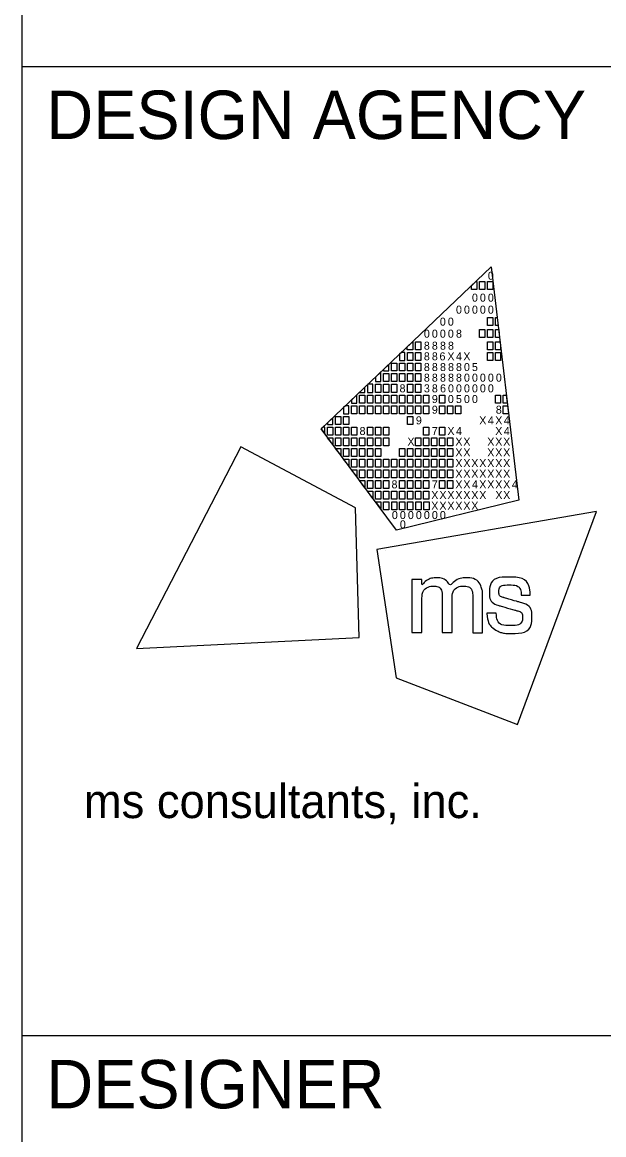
# Model space of a CAD drawing. Extents: x -3.6 to 34, y 0 to 22.
# Drawn here: x 32 to 33.201, y 2.295 to 4.591 of the extents above; entities that cross this region are included whole.
import ezdxf

# ---------------------------------------------------------------- set-up
doc = ezdxf.new("R2010")
doc.units = 0
for name, color, linetype in [('Default', 7, 'Continuous'), ('SH_Border', 7, 'Continuous'), ('SH_Data', 7, 'Continuous')]:
    doc.layers.add(name, color=color, linetype=linetype)

msp = doc.modelspace()

# ---------------------------------------------------------------- linework, layer by layer
at = {"layer": 'Default'}
for p, q in [((32.6175, 3.7519), (32.9688, 4.0861)), ((32.9688, 4.0861), (32.9688, 4.0861)), ((32.9688, 4.0861), (33.0253, 3.6052)), ((32.773, 3.543), (32.6175, 3.7519)), ((33.0253, 3.6052), (32.773, 3.543))]:
    msp.add_line(p, q, dxfattribs=at)
for points in [[(32.9279, 4.0472), (32.9369, 4.0558), (32.9389, 4.0558), (32.9389, 4.0393), (32.9279, 4.0393)], [(32.9444, 4.0558), (32.9554, 4.0558), (32.9554, 4.0393), (32.9444, 4.0393)], [(32.9609, 4.0558), (32.9719, 4.0558), (32.9719, 4.0393), (32.9609, 4.0393)], [(32.9606, 3.9815), (32.9716, 3.9815), (32.9716, 3.965), (32.9606, 3.965)], [(32.9771, 3.9815), (32.9811, 3.9815), (32.983, 3.965), (32.9771, 3.965)], [(32.9441, 3.9567), (32.9551, 3.9567), (32.9551, 3.9402), (32.9441, 3.9402)], [(32.9606, 3.9567), (32.9716, 3.9567), (32.9716, 3.9402), (32.9606, 3.9402)], [(32.9771, 3.9567), (32.984, 3.9567), (32.9859, 3.9402), (32.9771, 3.9402)], [(32.7953, 3.9211), (32.8064, 3.9316), (32.8064, 3.9154), (32.7953, 3.9154)], [(32.8123, 3.9319), (32.8233, 3.9319), (32.8233, 3.9154), (32.8123, 3.9154)], [(32.9606, 3.9319), (32.9716, 3.9319), (32.9716, 3.9154), (32.9606, 3.9154)], [(32.9771, 3.9319), (32.9869, 3.9319), (32.9881, 3.9218), (32.9881, 3.9154), (32.9771, 3.9154)], [(32.7958, 3.9099), (32.8068, 3.9099), (32.8068, 3.8934), (32.7958, 3.8934)], [(32.8123, 3.9099), (32.8233, 3.9099), (32.8233, 3.8934), (32.8123, 3.8934)], [(32.9606, 3.9099), (32.9716, 3.9099), (32.9716, 3.8934), (32.9606, 3.8934)], [(32.9771, 3.9099), (32.9881, 3.9099), (32.9881, 3.8934), (32.9771, 3.8934)], [(32.7627, 3.8879), (32.7737, 3.8879), (32.7737, 3.8714), (32.7627, 3.8714)], [(32.7793, 3.8879), (32.7903, 3.8879), (32.7903, 3.8714), (32.7793, 3.8714)], [(32.7958, 3.8879), (32.8068, 3.8879), (32.8068, 3.8714), (32.7958, 3.8714)], [(32.8123, 3.8879), (32.8233, 3.8879), (32.8233, 3.8714), (32.8123, 3.8714)], [(32.7462, 3.8659), (32.7572, 3.8659), (32.7572, 3.8494), (32.7462, 3.8494)], [(32.7627, 3.8659), (32.7737, 3.8659), (32.7737, 3.8494), (32.7627, 3.8494)], [(32.7793, 3.8659), (32.7903, 3.8659), (32.7903, 3.8494), (32.7793, 3.8494)], [(32.7958, 3.8659), (32.8068, 3.8659), (32.8068, 3.8494), (32.7958, 3.8494)], [(32.8123, 3.8659), (32.8233, 3.8659), (32.8233, 3.8494), (32.8123, 3.8494)], [(32.7297, 3.8439), (32.7407, 3.8439), (32.7407, 3.8273), (32.7297, 3.8273)], [(32.7462, 3.8439), (32.7572, 3.8439), (32.7572, 3.8273), (32.7462, 3.8273)], [(32.7627, 3.8439), (32.7737, 3.8439), (32.7737, 3.8273), (32.7627, 3.8273)], [(32.7958, 3.8439), (32.8068, 3.8439), (32.8068, 3.8273), (32.7958, 3.8273)], [(32.8123, 3.8439), (32.8233, 3.8439), (32.8233, 3.8273), (32.8123, 3.8273)], [(32.6967, 3.8218), (32.7077, 3.8218), (32.7077, 3.8053), (32.6967, 3.8053)], [(32.7132, 3.8218), (32.7242, 3.8218), (32.7242, 3.8053), (32.7132, 3.8053)], [(32.7297, 3.8218), (32.7407, 3.8218), (32.7407, 3.8053), (32.7297, 3.8053)], [(32.7462, 3.8218), (32.7572, 3.8218), (32.7572, 3.8053), (32.7462, 3.8053)], [(32.7627, 3.8218), (32.7737, 3.8218), (32.7737, 3.8053), (32.7627, 3.8053)], [(32.7793, 3.8218), (32.7903, 3.8218), (32.7903, 3.8053), (32.7793, 3.8053)], [(32.7958, 3.8218), (32.8068, 3.8218), (32.8068, 3.8053), (32.7958, 3.8053)], [(32.8123, 3.8218), (32.8233, 3.8218), (32.8233, 3.8053), (32.8123, 3.8053)], [(32.8288, 3.8218), (32.8398, 3.8218), (32.8398, 3.8053), (32.8288, 3.8053)], [(32.8618, 3.8218), (32.8728, 3.8218), (32.8728, 3.8053), (32.8618, 3.8053)], [(32.9771, 3.8218), (32.9881, 3.8218), (32.9881, 3.8053), (32.9771, 3.8053)], [(32.9935, 3.8218), (32.9998, 3.8218), (33.0018, 3.8053), (32.9935, 3.8053)], [(32.6802, 3.7998), (32.6912, 3.7998), (32.6912, 3.7833), (32.6802, 3.7833)], [(32.6967, 3.7998), (32.7077, 3.7998), (32.7077, 3.7833), (32.6967, 3.7833)], [(32.7132, 3.7998), (32.7242, 3.7998), (32.7242, 3.7833), (32.7132, 3.7833)], [(32.7297, 3.7998), (32.7407, 3.7998), (32.7407, 3.7833), (32.7297, 3.7833)], [(32.7462, 3.7998), (32.7572, 3.7998), (32.7572, 3.7833), (32.7462, 3.7833)], [(32.7627, 3.7998), (32.7737, 3.7998), (32.7737, 3.7833), (32.7627, 3.7833)], [(32.7793, 3.7998), (32.7903, 3.7998), (32.7903, 3.7833), (32.7793, 3.7833)], [(32.7958, 3.7998), (32.8068, 3.7998), (32.8068, 3.7833), (32.7958, 3.7833)], [(32.8123, 3.7998), (32.8233, 3.7998), (32.8233, 3.7833), (32.8123, 3.7833)], [(32.8288, 3.7998), (32.8398, 3.7998), (32.8398, 3.7833), (32.8288, 3.7833)], [(32.8618, 3.7998), (32.8728, 3.7998), (32.8728, 3.7833), (32.8618, 3.7833)], [(32.8783, 3.7998), (32.8893, 3.7998), (32.8893, 3.7833), (32.8783, 3.7833)], [(32.8947, 3.7998), (32.9057, 3.7998), (32.9057, 3.7833), (32.8947, 3.7833)], [(32.9935, 3.7998), (33.0024, 3.7998), (33.0044, 3.7833), (32.9935, 3.7833)], [(32.6471, 3.7778), (32.6581, 3.7778), (32.6581, 3.7613), (32.6471, 3.7613)], [(32.6637, 3.7778), (32.6747, 3.7778), (32.6747, 3.7613), (32.6637, 3.7613)], [(32.7958, 3.7778), (32.8068, 3.7778), (32.8068, 3.7613), (32.7958, 3.7613)], [(32.6306, 3.7558), (32.6416, 3.7558), (32.6416, 3.7393), (32.6306, 3.7393)], [(32.6471, 3.7558), (32.6581, 3.7558), (32.6581, 3.7393), (32.6471, 3.7393)], [(32.6637, 3.7558), (32.6747, 3.7558), (32.6747, 3.7393), (32.6637, 3.7393)], [(32.6802, 3.7558), (32.6912, 3.7558), (32.6912, 3.7393), (32.6802, 3.7393)], [(32.7132, 3.7558), (32.7242, 3.7558), (32.7242, 3.7393), (32.7132, 3.7393)], [(32.7297, 3.7558), (32.7407, 3.7558), (32.7407, 3.7393), (32.7297, 3.7393)], [(32.7462, 3.7558), (32.7572, 3.7558), (32.7572, 3.7393), (32.7462, 3.7393)], [(32.8288, 3.7558), (32.8398, 3.7558), (32.8398, 3.7393), (32.8288, 3.7393)], [(32.8618, 3.7558), (32.8728, 3.7558), (32.8728, 3.7393), (32.8618, 3.7393)], [(32.6306, 3.7338), (32.6416, 3.7338), (32.6416, 3.72)], [(32.6471, 3.7338), (32.6581, 3.7338), (32.6581, 3.7173), (32.6471, 3.7173)], [(32.6637, 3.7338), (32.6747, 3.7338), (32.6747, 3.7173), (32.6637, 3.7173)], [(32.6802, 3.7338), (32.6912, 3.7338), (32.6912, 3.7173), (32.6802, 3.7173)], [(32.6967, 3.7338), (32.7077, 3.7338), (32.7077, 3.7173), (32.6967, 3.7173)], [(32.7132, 3.7338), (32.7242, 3.7338), (32.7242, 3.7173), (32.7132, 3.7173)], [(32.7297, 3.7338), (32.7407, 3.7338), (32.7407, 3.7173), (32.7297, 3.7173)], [(32.7462, 3.7338), (32.7572, 3.7338), (32.7572, 3.7173), (32.7462, 3.7173)], [(32.8123, 3.7338), (32.8233, 3.7338), (32.8233, 3.7173), (32.8123, 3.7173)], [(32.8288, 3.7338), (32.8398, 3.7338), (32.8398, 3.7173), (32.8288, 3.7173)], [(32.8453, 3.7338), (32.8563, 3.7338), (32.8563, 3.7173), (32.8453, 3.7173)], [(32.8618, 3.7338), (32.8728, 3.7338), (32.8728, 3.7173), (32.8618, 3.7173)], [(32.8783, 3.7338), (32.8893, 3.7338), (32.8893, 3.7173), (32.8783, 3.7173)], [(32.6471, 3.7117), (32.6581, 3.7117), (32.6581, 3.698)], [(32.6637, 3.7117), (32.6747, 3.7117), (32.6747, 3.6952), (32.6637, 3.6952)], [(32.6802, 3.7117), (32.6912, 3.7117), (32.6912, 3.6952), (32.6802, 3.6952)], [(32.6967, 3.7117), (32.7077, 3.7117), (32.7077, 3.6952), (32.6967, 3.6952)], [(32.7132, 3.7117), (32.7242, 3.7117), (32.7242, 3.6952), (32.7132, 3.6952)], [(32.7297, 3.7117), (32.7407, 3.7117), (32.7407, 3.6952), (32.7297, 3.6952)], [(32.7793, 3.7117), (32.7903, 3.7117), (32.7903, 3.6952), (32.7793, 3.6952)], [(32.7958, 3.7117), (32.8068, 3.7117), (32.8068, 3.6952), (32.7958, 3.6952)], [(32.8123, 3.7117), (32.8233, 3.7117), (32.8233, 3.6952), (32.8123, 3.6952)], [(32.8288, 3.7117), (32.8398, 3.7117), (32.8398, 3.6952), (32.8288, 3.6952)], [(32.8453, 3.7117), (32.8563, 3.7117), (32.8563, 3.6952), (32.8453, 3.6952)], [(32.8618, 3.7117), (32.8728, 3.7117), (32.8728, 3.6952), (32.8618, 3.6952)], [(32.8783, 3.7117), (32.8893, 3.7117), (32.8893, 3.6952), (32.8783, 3.6952)], [(32.6637, 3.6897), (32.6747, 3.6897), (32.6747, 3.676)], [(32.6747, 3.6897), (32.6747, 3.6897), (32.6747, 3.6897)], [(32.6802, 3.6897), (32.6912, 3.6897), (32.6912, 3.6732), (32.6802, 3.6732)], [(32.6967, 3.6897), (32.7077, 3.6897), (32.7077, 3.6732), (32.6967, 3.6732)], [(32.7132, 3.6897), (32.7242, 3.6897), (32.7242, 3.6732), (32.7132, 3.6732)], [(32.7297, 3.6897), (32.7407, 3.6897), (32.7407, 3.6732), (32.7297, 3.6732)], [(32.7462, 3.6897), (32.7572, 3.6897), (32.7572, 3.6732), (32.7462, 3.6732)], [(32.7627, 3.6897), (32.7737, 3.6897), (32.7737, 3.6732), (32.7627, 3.6732)], [(32.7793, 3.6897), (32.7903, 3.6897), (32.7903, 3.6732), (32.7793, 3.6732)], [(32.7958, 3.6897), (32.8068, 3.6897), (32.8068, 3.6732), (32.7958, 3.6732)], [(32.8123, 3.6897), (32.8233, 3.6897), (32.8233, 3.6732), (32.8123, 3.6732)], [(32.8288, 3.6897), (32.8398, 3.6897), (32.8398, 3.6732), (32.8288, 3.6732)], [(32.8453, 3.6897), (32.8563, 3.6897), (32.8563, 3.6732), (32.8453, 3.6732)], [(32.8618, 3.6897), (32.8728, 3.6897), (32.8728, 3.6732), (32.8618, 3.6732)], [(32.8783, 3.6897), (32.8893, 3.6897), (32.8893, 3.6732), (32.8783, 3.6732)], [(32.6802, 3.6677), (32.6912, 3.6677), (32.6912, 3.654)], [(32.6967, 3.6677), (32.7077, 3.6677), (32.7077, 3.6512), (32.6967, 3.6512)], [(32.7132, 3.6677), (32.7242, 3.6677), (32.7242, 3.6512), (32.7132, 3.6512)], [(32.7297, 3.6677), (32.7407, 3.6677), (32.7407, 3.6512), (32.7297, 3.6512)], [(32.7462, 3.6677), (32.7572, 3.6677), (32.7572, 3.6512), (32.7462, 3.6512)], [(32.7627, 3.6677), (32.7737, 3.6677), (32.7737, 3.6512), (32.7627, 3.6512)], [(32.7793, 3.6677), (32.7903, 3.6677), (32.7903, 3.6512), (32.7793, 3.6512)], [(32.7958, 3.6677), (32.8068, 3.6677), (32.8068, 3.6512), (32.7958, 3.6512)], [(32.8123, 3.6677), (32.8233, 3.6677), (32.8233, 3.6512), (32.8123, 3.6512)], [(32.8288, 3.6677), (32.8398, 3.6677), (32.8398, 3.6512), (32.8288, 3.6512)], [(32.8453, 3.6677), (32.8563, 3.6677), (32.8563, 3.6512), (32.8453, 3.6512)], [(32.8618, 3.6677), (32.8728, 3.6677), (32.8728, 3.6512), (32.8618, 3.6512)], [(32.8783, 3.6677), (32.8893, 3.6677), (32.8893, 3.6512), (32.8783, 3.6512)], [(32.7077, 3.6305), (32.6965, 3.6457), (32.7077, 3.6457)], [(32.7132, 3.6457), (32.7242, 3.6457), (32.7242, 3.6292), (32.7132, 3.6292)], [(32.7297, 3.6457), (32.7407, 3.6457), (32.7407, 3.6292), (32.7297, 3.6292)], [(32.7462, 3.6457), (32.7572, 3.6457), (32.7572, 3.6292), (32.7462, 3.6292)], [(32.7793, 3.6457), (32.7903, 3.6457), (32.7903, 3.6292), (32.7793, 3.6292)], [(32.7958, 3.6457), (32.8068, 3.6457), (32.8068, 3.6292), (32.7958, 3.6292)], [(32.8123, 3.6457), (32.8233, 3.6457), (32.8233, 3.6292), (32.8123, 3.6292)], [(32.8288, 3.6457), (32.8398, 3.6457), (32.8398, 3.6292), (32.8288, 3.6292)], [(32.8618, 3.6457), (32.8728, 3.6457), (32.8728, 3.6292), (32.8618, 3.6292)], [(32.8783, 3.6457), (32.8893, 3.6457), (32.8893, 3.6292), (32.8783, 3.6292)], [(32.724, 3.6082), (32.7132, 3.6237), (32.7242, 3.6237)], [(32.7297, 3.6237), (32.7407, 3.6237), (32.7407, 3.6072), (32.7297, 3.6072)], [(32.7462, 3.6237), (32.7572, 3.6237), (32.7572, 3.6072), (32.7462, 3.6072)], [(32.7627, 3.6237), (32.7737, 3.6237), (32.7737, 3.6072), (32.7627, 3.6072)], [(32.7793, 3.6237), (32.7903, 3.6237), (32.7903, 3.6072), (32.7793, 3.6072)], [(32.7958, 3.6237), (32.8068, 3.6237), (32.8068, 3.6072), (32.7958, 3.6072)], [(32.8123, 3.6237), (32.8233, 3.6237), (32.8233, 3.6072), (32.8123, 3.6072)], [(32.8288, 3.6237), (32.8398, 3.6237), (32.8398, 3.6072), (32.8288, 3.6072)], [(32.7302, 3.6017), (32.7407, 3.6017), (32.7408, 3.5875)], [(32.7463, 3.6017), (32.7573, 3.6017), (32.7573, 3.5852), (32.7463, 3.5852)], [(32.763, 3.6017), (32.774, 3.6017), (32.774, 3.5852), (32.763, 3.5852)], [(32.7794, 3.6017), (32.7904, 3.6017), (32.7904, 3.5852), (32.7794, 3.5852)], [(32.796, 3.6017), (32.807, 3.6017), (32.807, 3.5852), (32.796, 3.5852)], [(32.8129, 3.6017), (32.8239, 3.6017), (32.8239, 3.5851), (32.8129, 3.5851)], [(32.8296, 3.6017), (32.8406, 3.6017), (32.8406, 3.5851), (32.8296, 3.5851)]]:
    msp.add_lwpolyline(points, close=True, dxfattribs=at)
for points in [[(32.7903, 3.9099), (32.7836, 3.9099), (32.7793, 3.9058), (32.7793, 3.8934), (32.7903, 3.8934), (32.7903, 3.9099)], [(32.7572, 3.8849), (32.7462, 3.8744), (32.7462, 3.8714), (32.7572, 3.8714), (32.7572, 3.8849)], [(32.7407, 3.8691), (32.7297, 3.8587), (32.7297, 3.8494), (32.7407, 3.8494), (32.7407, 3.8691)], [(32.7077, 3.8377), (32.6968, 3.8273), (32.7077, 3.8273), (32.7077, 3.8377)], [(32.7242, 3.8439), (32.7141, 3.8439), (32.7132, 3.843), (32.7132, 3.8273), (32.7242, 3.8273), (32.7242, 3.8439)], [(32.6912, 3.822), (32.6802, 3.8115), (32.6802, 3.8053), (32.6912, 3.8053), (32.6912, 3.822)], [(32.6747, 3.7998), (32.6679, 3.7998), (32.6637, 3.7958), (32.6637, 3.7833), (32.6747, 3.7833), (32.6747, 3.7998)], [(32.6416, 3.7749), (32.6306, 3.7644), (32.6306, 3.7613), (32.6416, 3.7613), (32.6416, 3.7749)], [(32.6251, 3.7558), (32.6216, 3.7558), (32.6175, 3.7519), (32.6251, 3.7417), (32.6251, 3.7558)], [(32.4512, 3.7149), (32.2359, 3.2988), (32.6956, 3.3215), (32.6884, 3.5892), (32.4512, 3.7149)], [(33.0229, 3.1422), (33.1859, 3.5814), (32.7324, 3.5029), (32.7722, 3.2381), (33.0229, 3.1422)]]:
    msp.add_lwpolyline(points, dxfattribs=at)
for points in [[(32.8048, 3.3315), (32.8048, 3.3315), (32.8048, 3.4409), (32.8048, 3.4409), (32.8048, 3.4409), (32.8255, 3.4409), (32.8255, 3.4409), (32.8255, 3.4409), (32.8255, 3.4297), (32.8255, 3.4297), (32.8346, 3.4399), (32.8457, 3.4445), (32.8555, 3.4445), (32.8688, 3.4445), (32.8791, 3.4372), (32.8837, 3.4266), (32.8915, 3.4381), (32.905, 3.4446), (32.9166, 3.4446), (32.9325, 3.4446), (32.9451, 3.435), (32.9494, 3.4213), (32.9494, 3.4212), (32.9494, 3.4212), (32.9494, 3.4212), (32.9501, 3.419), (32.9506, 3.4172), (32.9506, 3.4071), (32.9506, 3.4071), (32.9506, 3.3314), (32.9506, 3.3314), (32.9506, 3.3314), (32.9303, 3.3314), (32.9303, 3.3314), (32.9303, 3.3314), (32.9303, 3.4048), (32.9303, 3.4048), (32.9303, 3.4201), (32.9219, 3.4274), (32.911, 3.4274), (32.8995, 3.4274), (32.8879, 3.4171), (32.8879, 3.4001), (32.8879, 3.4001), (32.8879, 3.3315), (32.8879, 3.3315), (32.8879, 3.3315), (32.8674, 3.3315), (32.8674, 3.3315), (32.8674, 3.3315), (32.8674, 3.4059), (32.8674, 3.4059), (32.8674, 3.4203), (32.8588, 3.4274), (32.8496, 3.4274), (32.8384, 3.4274), (32.8254, 3.417), (32.8254, 3.3962), (32.8254, 3.3962), (32.8254, 3.3315), (32.8254, 3.3315), (32.8254, 3.3315), (32.8048, 3.3315), (32.8048, 3.3315)], [(32.9595, 3.3709), (32.9595, 3.3709), (32.9595, 3.3717), (32.9595, 3.3717), (32.9595, 3.3717), (32.9603, 3.3717), (32.9603, 3.3717), (32.9603, 3.3717), (32.9783, 3.3717), (32.9783, 3.3717), (32.9783, 3.3717), (32.9789, 3.3717), (32.9789, 3.3717), (32.9789, 3.3717), (32.979, 3.371), (32.979, 3.371), (32.9803, 3.3554), (32.9887, 3.346), (33.009, 3.346), (33.0273, 3.346), (33.0333, 3.3554), (33.0333, 3.3631), (33.0333, 3.3732), (33.0256, 3.3758), (33.0175, 3.378), (33.0175, 3.378), (32.987, 3.3867), (32.987, 3.3867), (32.972, 3.3909), (32.9648, 3.4019), (32.9648, 3.4142), (32.9648, 3.4303), (32.9768, 3.4462), (33.0052, 3.4462), (33.0348, 3.4462), (33.0489, 3.4285), (33.0489, 3.4095), (33.0489, 3.4095), (33.0489, 3.4087), (33.0489, 3.4087), (33.0489, 3.4087), (33.0482, 3.4087), (33.0482, 3.4087), (33.0482, 3.4087), (33.0312, 3.4087), (33.0312, 3.4087), (33.0312, 3.4087), (33.0305, 3.4087), (33.0305, 3.4087), (33.0305, 3.4087), (33.0305, 3.4094), (33.0305, 3.4094), (33.0301, 3.4208), (33.0226, 3.43), (33.0056, 3.43), (32.9891, 3.43), (32.9843, 3.4218), (32.9843, 3.4157), (32.9843, 3.4108), (32.9869, 3.4059), (32.9959, 3.4033), (32.9959, 3.4033), (33.0255, 3.3948), (33.0255, 3.3948), (33.0462, 3.3889), (33.0527, 3.3777), (33.0527, 3.3639), (33.0527, 3.3462), (33.041, 3.3298), (33.0087, 3.3298), (32.9952, 3.3298), (32.9877, 3.3321), (32.9823, 3.3348), (32.969, 3.3414), (32.9609, 3.3536), (32.9595, 3.3709)]]:
    msp.add_open_spline(points, degree=3, dxfattribs=at)
at = {"layer": 'SH_Border'}
for p, q in [((32, 0.5), (32, 21.5)), ((32, 4.5), (33.5, 4.5)), ((32, 2.5), (33.5, 2.5))]:
    msp.add_line(p, q, dxfattribs=at)
at = {"layer": 'SH_Data'}
msp.add_line((32.75, 3.5), (32.75, 3.5), dxfattribs=at)

# ---------------------------------------------------------------- texts
at = {"layer": 'Default'}
for s, p in [('0', (32.9617, 4.0597)), ('0', (32.9288, 4.0145)), ('0', (32.9452, 4.0145)), ('0', (32.9617, 4.0145)), ('0', (32.8958, 3.9897)), ('0', (32.9123, 3.9897)), ('0', (32.9288, 3.9897)), ('0', (32.9452, 3.9897)), ('0', (32.9617, 3.9897)), ('0', (32.8625, 3.965)), ('0', (32.879, 3.965)), ('0', (32.8295, 3.9402)), ('0', (32.846, 3.9402)), ('0', (32.8625, 3.9402)), ('0', (32.879, 3.9402)), ('8', (32.8958, 3.9402)), ('8', (32.8295, 3.9154)), ('8', (32.846, 3.9154)), ('8', (32.8628, 3.9154)), ('8', (32.8793, 3.9154)), ('8', (32.8295, 3.8934)), ('8', (32.846, 3.8934)), ('6', (32.8618, 3.8934)), ('X', (32.8781, 3.8934)), ('4', (32.8958, 3.8934)), ('X', (32.911, 3.8934)), ('8', (32.8295, 3.8713)), ('8', (32.846, 3.8713)), ('8', (32.8628, 3.8713)), ('8', (32.8794, 3.8713)), ('8', (32.8958, 3.8713)), ('0', (32.9123, 3.8713)), ('5', (32.9287, 3.8713)), ('8', (32.8295, 3.8494)), ('8', (32.846, 3.8494)), ('8', (32.8628, 3.8494)), ('8', (32.8794, 3.8494)), ('8', (32.8958, 3.8494)), ('0', (32.9123, 3.8494)), ('0', (32.9288, 3.8494)), ('0', (32.9452, 3.8494)), ('0', (32.9617, 3.8494)), ('0', (32.9782, 3.8494)), ('8', (32.7793, 3.8273)), ('3', (32.8295, 3.8273)), ('8', (32.846, 3.8273)), ('6', (32.8629, 3.8273)), ('0', (32.8793, 3.8273)), ('0', (32.8958, 3.8273)), ('0', (32.9123, 3.8273)), ('0', (32.9288, 3.8273)), ('0', (32.9452, 3.8273)), ('0', (32.9617, 3.8273)), ('9', (32.846, 3.8053)), ('0', (32.879, 3.8053)), ('5', (32.8957, 3.8053)), ('0', (32.9123, 3.8053)), ('0', (32.9288, 3.8053)), ('9', (32.846, 3.7833)), ('8', (32.9781, 3.7833)), ('9', (32.813, 3.7613)), ('X', (32.9439, 3.7613)), ('4', (32.9617, 3.7613)), ('X', (32.9769, 3.7613)), ('4', (32.9946, 3.7613)), ('8', (32.6967, 3.7393)), ('7', (32.846, 3.7393)), ('X', (32.8781, 3.7393)), ('4', (32.8958, 3.7393)), ('X', (32.9769, 3.7393)), ('4', (32.9946, 3.7393)), ('X', (32.7955, 3.7173)), ('X', (32.8945, 3.7173)), ('X', (32.911, 3.7173)), ('X', (32.9604, 3.7173)), ('X', (32.9769, 3.7173)), ('X', (32.9933, 3.7173)), ('X', (32.8945, 3.6952)), ('X', (32.911, 3.6952)), ('X', (32.9604, 3.6952)), ('X', (32.9769, 3.6952)), ('X', (32.9933, 3.6952)), ('X', (32.8945, 3.6732)), ('X', (32.911, 3.6732)), ('X', (32.9274, 3.6732)), ('X', (32.9439, 3.6732)), ('X', (32.9604, 3.6732)), ('X', (32.9769, 3.6732)), ('X', (32.9933, 3.6732)), ('X', (32.8945, 3.6512)), ('X', (32.911, 3.6512)), ('X', (32.9274, 3.6512)), ('X', (32.9439, 3.6512)), ('X', (32.9604, 3.6512)), ('X', (32.9769, 3.6512)), ('X', (32.9933, 3.6512)), ('8', (32.7627, 3.6292)), ('7', (32.846, 3.6292)), ('X', (32.8945, 3.6292)), ('X', (32.911, 3.6292)), ('4', (32.9288, 3.6292)), ('X', (32.9439, 3.6292)), ('X', (32.9604, 3.6292)), ('X', (32.9769, 3.6292)), ('X', (32.9933, 3.6292)), ('4', (33.0111, 3.6292)), ('X', (32.8447, 3.6072)), ('X', (32.8616, 3.6072)), ('X', (32.878, 3.6072)), ('X', (32.8945, 3.6072)), ('X', (32.911, 3.6072)), ('X', (32.9274, 3.6072)), ('X', (32.9439, 3.6072)), ('X', (32.9771, 3.6072)), ('X', (32.9933, 3.6072)), ('0', (32.7634, 3.5659)), ('0', (32.7799, 3.5659)), ('0', (32.7965, 3.5659)), ('0', (32.813, 3.5659)), ('0', (32.8295, 3.5659)), ('X', (32.8447, 3.5851)), ('0', (32.846, 3.5659)), ('X', (32.8616, 3.5851)), ('0', (32.8625, 3.5659)), ('X', (32.878, 3.5851)), ('X', (32.8945, 3.5851)), ('X', (32.911, 3.5851)), ('X', (32.9274, 3.5851)), ('0', (32.7799, 3.5467))]:
    msp.add_text(s, height=0.0165, rotation=360, dxfattribs=at).set_placement(p)
at = {"layer": 'SH_Border'}
msp.add_text('ms consultants, inc.', height=0.07, rotation=360, dxfattribs=at).set_placement((32.1273, 2.9489))
at = {"layer": 'SH_Data'}
for s, p in [('DESIGN AGENCY', (32.05, 4.35)), ('DESIGNER', (32.05, 2.35))]:
    msp.add_text(s, height=0.1, dxfattribs=at).set_placement(p)

doc.saveas('drawing.dxf')
